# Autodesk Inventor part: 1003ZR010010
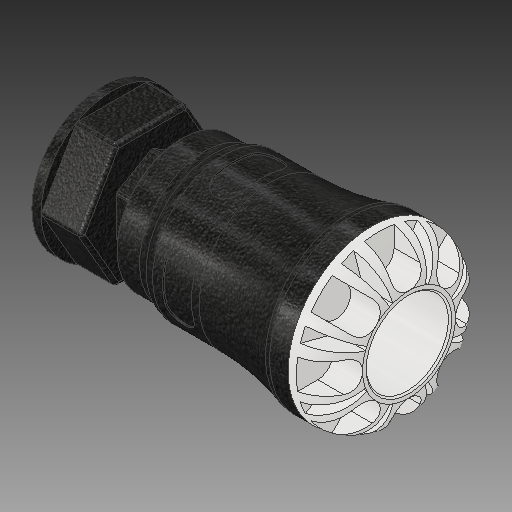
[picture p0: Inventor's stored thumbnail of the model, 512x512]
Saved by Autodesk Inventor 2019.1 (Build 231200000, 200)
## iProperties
Created: 2016-12
Part Number: 1003ZR010010
Material: PVC-Piping
Description: PLASSON FEMALE ADAPTOR WITH FREE NUT 1''CTS x 1''
Document SubType Name: Modeling
Designer: KIM
Mass: 664.23 g
Surface Area: 733.008 cm^2
Volume: 474.45 cm^3
Density: 1.4 g/cm^3
Appearance: Black Cast
Author: KIM
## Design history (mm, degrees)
derived "1003ZR.ipt"
feature "Solid1::1003ZR.ipt"
feature "Solid2::1003ZR.ipt"
tag "TaggingFeature1"
body "Solid1"
body "Solid2"
other parameters: "d1" = 20.16252, "d2" = 28.45, "d3" = 32.13275, "d4" = 57.912, "d6" = 48.006, "d8" = 49.2252, "d13" = 10.3117, "d14" = 10.3117, "d15" = 0, "d17" = 360 deg, "d19" = 8 deg, "d20" = 0.569, "d21" = 0.569, "d22" = 8 deg, "d24" = 0, "d26" = 360 deg, "d32" = 5.7912, "d33" = 5.7912, "d39" = 0.55893, "d42" = 18.631, "d43" = 45.17136, "d46" = 2.37083, "d48" = 17.69945, "d50" = 6.03504, "d51" = 0.57912, "d54" = 9.9575, "d55" = 6.259, "d57" = 17.52201, "d58" = 0, "d68" = 360 deg, "d72" = 0.569, "d74" = 0, "d76" = 8.46387, "d78" = 78.994, "d79" = 12.7, "d80" = 105.918, "d81" = 3.17754, "d82" = 16.94688, "d83" = 18.631, "d84" = 14.9048, "d85" = 10.5918, "d87" = 13.76934, "d88" = 0, "d90" = 0, "d91" = 1.27, "d_" = 28.45, "E_" = 57.912, "H_" = 105.918, "l_" = 48.006, "G_" = 18.631, "d9" = 12.88963, "d11" = 57.912, "d12" = 32.13275, "d49" = 18.288
